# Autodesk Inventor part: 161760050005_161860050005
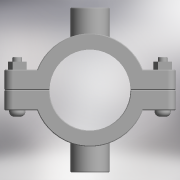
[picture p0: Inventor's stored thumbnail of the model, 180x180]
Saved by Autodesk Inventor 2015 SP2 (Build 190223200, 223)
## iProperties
Created: 2017-05
Part Number: 161760050005_161860050005
Material: Generic
Description: PLASSON DOUBLE SADDLE 50-1"/2"
Document SubType Name: Modeling
Designer: KIM
Density: 1 g/cm^3
Appearance: Default
Author: KIM
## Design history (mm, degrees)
derived "16176.ipt"
feature "Solid1::16176.ipt"
feature "Solid2::16176.ipt"
tag "TaggingFeature1"
body "Solid1"
body "Solid2"
other parameters: "d1" = 106, "d2" = 25, "d4" = 73, "d5" = 0, "d6" = 5.3, "d7" = 106, "d8" = 0.1, "d10" = 0, "d11" = 0.5, "d20" = 0.5, "d23" = 0.5, "d37" = 8, "d38" = 33, "d39" = 0, "d40" = 3, "d41" = 5, "d42" = 0, "d43" = 6, "d44" = 3, "d45" = 0, "d46" = 0.5, "d52" = 18.631, "d53" = 18, "d54" = 0, "d55" = 16, "d57" = 0, "d58" = 54, "d60" = 0, "d63" = 36.5, "d66" = 0, "d67" = 102, "d68" = 24.2203, "d69" = 18.631, "d70" = 18, "d71" = 0, "d72" = 16, "d74" = 0, "d75" = 0.5, "B_" = 16, "G_" = 18.631, "A_" = 51, "L_" = 106, "L_1" = 73, "l_2" = 18
